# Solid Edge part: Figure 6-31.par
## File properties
Author: Ashutosh-CADCIM
Template: iso metric part.par
Last saved by: Ashutosh-CADCIM
Revision: 1
Application: Solid Edge
Accuracy: 0.990
Username: Ashutosh-CADCIM
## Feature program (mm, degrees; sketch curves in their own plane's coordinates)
sketch for "unnamed Protrusion 1" plane through (0, 0, 0) normal (0, -1, 0) x-axis (1, 0, 0)
  line (89.3163, 14.2634) -> (15.6219, 14.2634)
  line (15.6219, 14.2634) -> (15.6219, 72.336)
  line (15.6219, 72.336) -> (0, 72.336)
  line (0, 72.336) -> (0, 0)
  line (0, 0) -> (89.3163, 0)
  line (89.3163, 0) -> (89.3163, 14.2634)
extrude "unnamed Protrusion 1" add finite 120 symmetric
fillet "Round_2" radius 10  VertexRadius1 = 10 mm; VertexRadius2 = 25 mm; VertexRadius3 = 15 mm
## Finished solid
Body 1: solid body, 9 faces, 21 edges, 14 vertices.
  Faces by surface: plane 8, spline 1
  Edges by curve: line 17, intersection 2, spline 2
Bounding box of the edges (mm; curved faces can reach further): 89.316 x 120.000 x 72.336, from (0, -60, 0) to (89.3163, 60, 72.336).
Planar faces by outward normal: +x 2, +y 1, +z 2, -x 1, -y 1, -z 1
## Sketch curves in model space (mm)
line (0, 0, 0) -> (89.3163, 0, 0)
line (89.3163, 0, 0) -> (89.3163, 0, 14.2634)
line (89.3163, 0, 14.2634) -> (15.6219, 0, 14.2634)
line (15.6219, 0, 14.2634) -> (15.6219, 0, 72.336)
line (15.6219, 0, 72.336) -> (0, 0, 72.336)
line (0, 0, 72.336) -> (0, 0, 0)
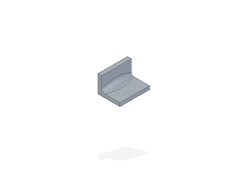
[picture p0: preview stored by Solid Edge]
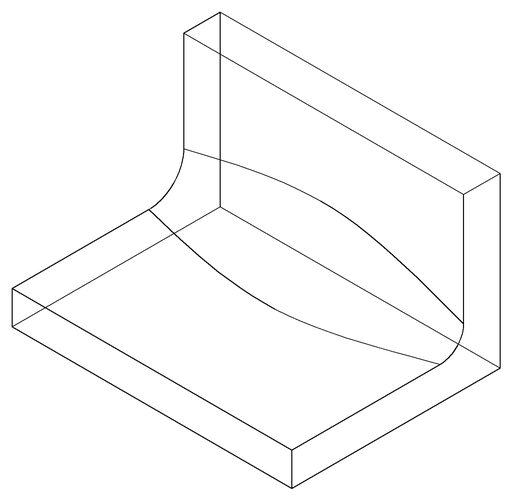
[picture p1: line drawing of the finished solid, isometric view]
